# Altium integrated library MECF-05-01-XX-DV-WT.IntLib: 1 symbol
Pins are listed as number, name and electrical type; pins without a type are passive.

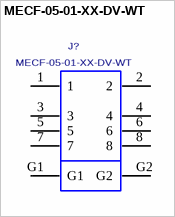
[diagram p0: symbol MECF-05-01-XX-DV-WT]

## MECF-05-01-XX-DV-WT
designator J?
MECF .050" EDGE CARD ASSEMBLY.; MANUFACTURER: SAMTEC
footprint MECF-05-01-XX-DV-WT
pins: 1, 2, 3, 4, 5, 6, 7, 8, G1, G2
